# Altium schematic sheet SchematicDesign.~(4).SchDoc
size A4
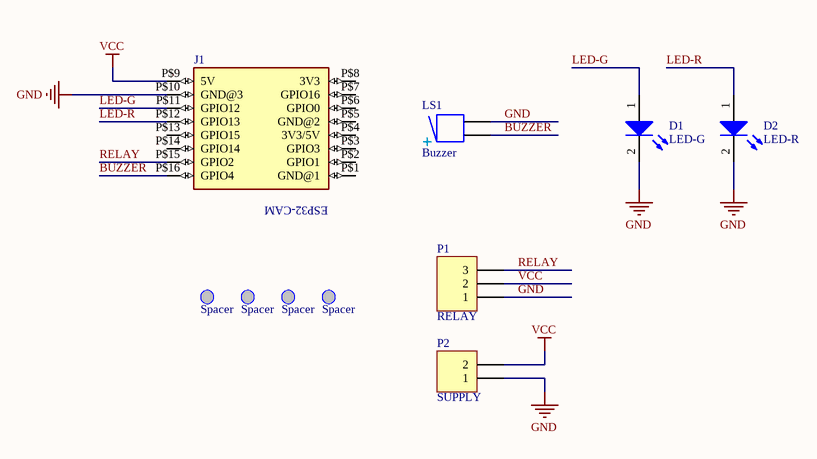
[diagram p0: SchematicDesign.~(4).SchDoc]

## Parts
1  Spacer  [Spacer]
2  Spacer  [Spacer]
3  Spacer  [Spacer]
4  Spacer  [Spacer]
D1  LED-G  [LED]
D2  LED-R  [LED]
J1  ESP32-CAM  [ESP32-CAM]  (value not drawn)
LS1  Buzzer  [BUZZER]
P1  RELAY  [HDR1X3]
P2  SUPPLY  [Term.Block 2pin]

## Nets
GND: D1.2(K) D2.2(K) J1.P$10(GND@3) LS1.2 P1.1 P2.0(1)
VCC: J1.P$9(5V) P1.2 P2.1(2)
BUZZER: J1.P$16(GPIO4) LS1.1
LED-G: D1.1(A) J1.P$11(GPIO12)
LED-R: D2.1(A) J1.P$12(GPIO13)
RELAY: J1.P$15(GPIO2) P1.3

Not connected (* = marked no-connect by the designer): J1 P$1(GND@1) P$2(GPIO1) P$3(GPIO3) P$4(3V3/5V) P$5(GND@2) P$6(GPIO0) P$7(GPIO16) P$8(3V3) P$13(GPIO15) P$14(GPIO14)

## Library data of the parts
D1 D2 = LED: LED 3mm or 5mm
J1 = ESP32-CAM: ESP32 ESP32 Transceiver; 802.11 a/b/g/n (Wi-Fi, WiFi, WLAN), BluetoothÂ® Smart 4.x Low Energy (BLE) Evaluation Board; MF: AI-Thinker
LS1 = Buzzer: Magnetic Transducer Buzzer
P1 = Header 3: Header, 3-Pin
P2 = Terminal Block 2pin: Terminal Block, 2-Pin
